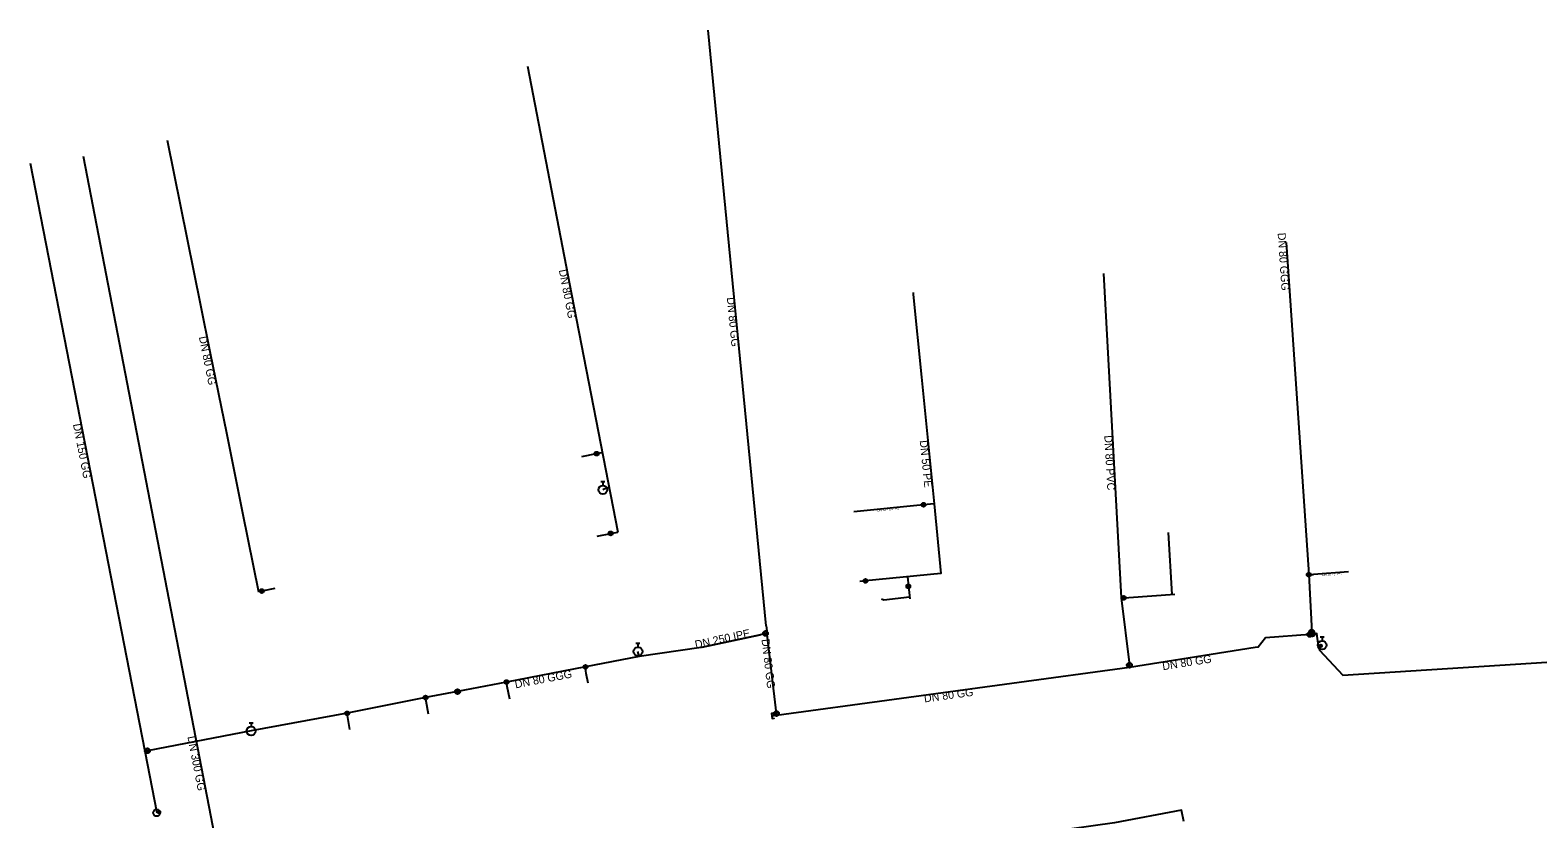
# Model space of a CAD drawing. Extents: x -452548 to -451108, y -1100145 to -1099658.
# Drawn here: x -452039.2 to -451735.5, y -1099878.8 to -1099719.9 of the extents above; entities that cross this region are included whole.
import ezdxf

# ---------------------------------------------------------------- set-up
doc = ezdxf.new("R2010")
doc.units = 0
for name, color, linetype in [('_hydrantova_odbocka_', 7, 'Continuous'), ('_pripojka_prevzato_z_dokumentace_', 7, 'Continuous'), ('_pripojka_priblizne_', 7, 'Continuous'), ('_voda_smvak_prevzato_z_dokumentace_', 7, 'Continuous'), ('_vodovodni_chranicka_', 7, 'Continuous'), ('Default', 7, 'Continuous'), ('MoLevel 27', 7, 'Continuous'), ('MoLevel 28', 7, 'Continuous'), ('MoLevel 30', 7, 'Continuous'), ('MoLevel 42', 7, 'Continuous'), ('MoLevel 43', 7, 'Continuous'), ('MoLevel 46', 7, 'Continuous'), ('MoLevel 53', 7, 'Continuous'), ('MoLevel 55', 7, 'Continuous'), ('MoLevel 60', 7, 'Continuous')]:
    doc.layers.add(name, color=color, linetype=linetype)

# ---------------------------------------------------------------- blocks, each defined once
blk = doc.blocks.new('_uzaver_')
at = {"layer": 'Default'}
for p, q in [((-0.000035, -0.000035), (0.000035, 0.000035)), ((0.000035, -0.000035), (-0.000035, 0.000035))]:
    blk.add_line(p, q, dxfattribs=at)
for radius in [0.00005, 0.0000025]:
    blk.add_circle((0, 0), radius, dxfattribs=at)
blk = doc.blocks.new('_uzaver_pripojka_')
at = {"layer": 'Default'}
for p, q in [((-0.000035, -0.000035), (0.000035, 0.000035)), ((0.000035, -0.000035), (-0.000035, 0.000035))]:
    blk.add_line(p, q, dxfattribs=at)
for radius in [0.00005, 0.0000025]:
    blk.add_circle((0, 0), radius, dxfattribs=at)
blk = doc.blocks.new('_hydrant_voda_')
at = {"layer": 'Default'}
for p, q in [((-0.000023, 0.000095), (0.000023, 0.000095)), ((0, 0.000095), (0, 0.00005))]:
    blk.add_line(p, q, dxfattribs=at)
blk.add_circle((0, 0), 0.00005, dxfattribs=at)
blk = doc.blocks.new('_zaslepeni_')
at = {"layer": 'Default'}
blk.add_lwpolyline([(-0.00004, -0.00005), (0, -0.00005), (0, 0.00005), (-0.00004, 0.00005), (-0.00004, 0.00005)], dxfattribs=at)
blk = doc.blocks.new('_sachta_voda_')
at = {"layer": 'Default'}
blk.add_circle((0, 0), 0.000035, dxfattribs=at)
blk = doc.blocks.new('_poklop_voda_')
at = {"layer": 'Default'}
blk.add_lwpolyline([(-0.00002, 0.00002), (0.00002, 0.00002), (0.00002, -0.00002), (-0.00002, -0.00002), (-0.00002, 0.00002)], dxfattribs=at)

msp = doc.modelspace()

# ---------------------------------------------------------------- linework, layer by layer
at = {"layer": '_hydrantova_odbocka_'}
for points in [[(-451922.54, -1099812.09), (-451923.04, -1099812.19), (-451923.79, -1099812.49)], [(-451779.62, -1099844.01), (-451779.19, -1099843.92), (-451778.92, -1099843.79)], [(-451916.47, -1099846.08), (-451916.6, -1099845.56), (-451916.73, -1099845.07)]]:
    msp.add_lwpolyline(points, dxfattribs=at)
at = {"layer": '_pripojka_prevzato_z_dokumentace_'}
for p, q in [((-451781.6, -1099829.59), (-451780.63, -1099829.54)), ((-451773.61, -1099829.04), (-451780.63, -1099829.54)), ((-451872.01, -1099830.93), (-451870.9, -1099830.84)), ((-451926.72, -1099851.48), (-451927.13, -1099849.51)), ((-451942.51, -1099854.65), (-451943.07, -1099852.15)), ((-451958.9, -1099857.7), (-451959.36, -1099855.05)), ((-451974.79, -1099860.76), (-451975.14, -1099858.33))]:
    msp.add_line(p, q, dxfattribs=at)
for points in [[(-451928.03, -1099805.8), (-451925.05, -1099805.22), (-451923.92, -1099805)], [(-451857.09, -1099815.31), (-451859.19, -1099815.52), (-451873.23, -1099816.92)], [(-451924.94, -1099821.82), (-451922.21, -1099821.28), (-451920.81, -1099821.02)], [(-451989.9, -1099832.39), (-451992.5, -1099832.89), (-451993.15, -1099833.02)], [(-451862.45, -1099830), (-451862.26, -1099831.94), (-451861.98, -1099834.43)], [(-451819.38, -1099834.29), (-451818.87, -1099834.26), (-451817.85, -1099834.18), (-451808.61, -1099833.55)], [(-451927.13, -1099849.51), (-451927.19, -1099848.95), (-451927.28, -1099848.16)], [(-451943.07, -1099852.15), (-451943.13, -1099851.65), (-451943.19, -1099851.22)], [(-451959.36, -1099855.05), (-451959.42, -1099854.76), (-451959.49, -1099854.35)], [(-451975.14, -1099858.33), (-451975.22, -1099857.94), (-451975.3, -1099857.52)]]:
    msp.add_lwpolyline(points, dxfattribs=at)
at = {"layer": '_pripojka_priblizne_'}
msp.add_line((-451809.14, -1099833.58), (-451809.83, -1099821.13), dxfattribs=at)
msp.add_lwpolyline([(-451862.01, -1099834.12), (-451867.18, -1099834.74), (-451867.66, -1099834.53)], dxfattribs=at)
at = {"layer": '_voda_smvak_prevzato_z_dokumentace_'}
for p, q in [((-451890.88, -1099839.87), (-451902.55, -1099719.92)), ((-452039.15, -1099746.71), (-452016.08, -1099865.12)), ((-452003.12, -1099876.35), (-452028.42, -1099745.38)), ((-451890.72, -1099841.41), (-451891.03, -1099841.43)), ((-451888.83, -1099857.57), (-451890.71, -1099841.66)), ((-451780.99, -1099841.55), (-451781.4, -1099841.63)), ((-451781.01, -1099841.17), (-451780.99, -1099841.55)), ((-451780.87, -1099841.53), (-451780.99, -1099841.55)), ((-451792.38, -1099844.27), (-451817.68, -1099848.29)), ((-451817.72, -1099847.83), (-451817.68, -1099848.29)), ((-451817.68, -1099848.29), (-451888.79, -1099857.95)), ((-451888.79, -1099857.95), (-451889.77, -1099858.06)), ((-451888.79, -1099857.95), (-451888.83, -1099857.57)), ((-451994.65, -1099861.08), (-452015.54, -1099865.07)), ((-452015.53, -1099865.07), (-452016.08, -1099865.12)), ((-452016.08, -1099865.12), (-452013.65, -1099877.56))]:
    msp.add_line(p, q, dxfattribs=at)
for points in [[(-451939, -1099727.2), (-451930.1, -1099773.11), (-451920.81, -1099821.02)], [(-452011.58, -1099742.08), (-452004.84, -1099775.33), (-452002.89, -1099784.98), (-451999.63, -1099801.02), (-451996.36, -1099817.17), (-451993.15, -1099833.02)], [(-451786.13, -1099762.72), (-451785.48, -1099772.43), (-451781.6, -1099829.59), (-451781.01, -1099841.17)], [(-451822.98, -1099768.93), (-451819.38, -1099834.29), (-451817.72, -1099847.83)], [(-451861.32, -1099772.73), (-451861.28, -1099773.14), (-451859.62, -1099789.82), (-451857.09, -1099815.31), (-451855.7, -1099829.33), (-451870.9, -1099830.84)], [(-451891.03, -1099841.43), (-451892.01, -1099841.7), (-451903.97, -1099844.26), (-451916.47, -1099846.08), (-451927.28, -1099848.16), (-451943.19, -1099851.22), (-451953.07, -1099853.15)], [(-451890.88, -1099839.87), (-451890.72, -1099841.41), (-451890.71, -1099841.66)], [(-451781.4, -1099841.63), (-451790.31, -1099842.31), (-451791.77, -1099844.2), (-451792.38, -1099844.27)], [(-451779.64, -1099843.93), (-451779.98, -1099841.43), (-451780.87, -1099841.53), (-451780.87, -1099841.53)], [(-451779.64, -1099843.93), (-451779.43, -1099844.82), (-451774.74, -1099849.86), (-451705.18, -1099845.41), (-451704.49, -1099845.24)], [(-451953.07, -1099853.15), (-451959.49, -1099854.35), (-451975.3, -1099857.52), (-451994.65, -1099861.08)], [(-451978.75, -1099992.6), (-451982.47, -1099975.18), (-451984.85, -1099964.79), (-451987.8, -1099951.84), (-451992.55, -1099931.06), (-452003.12, -1099876.35)], [(-451806.74, -1099879.29), (-451807.26, -1099877.03), (-451820.76, -1099879.61), (-451834.59, -1099881.54), (-451839.74, -1099882.46), (-451857.41, -1099885.86), (-451884.96, -1099892.07), (-451884.96, -1099892.47)]]:
    msp.add_lwpolyline(points, dxfattribs=at)
at = {"layer": '_vodovodni_chranicka_'}
msp.add_line((-451903.78, -1099844.21), (-451892.1, -1099841.68), dxfattribs=at)

# ---------------------------------------------------------------- block references
at = {"layer": 'MoLevel 27'}
for p, xscale, yscale, rotation in [((-451891.03, -1099841.43), 10000.000000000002, 10000, 7.800187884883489), ((-451781.4, -1099841.63), 10000, 10000.000000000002, 7.23692202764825), ((-451781.01, -1099841.17), 10000.000000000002, 9999.999999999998, 92.8395243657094), ((-451780.87, -1099841.53), 10000, 10000, 4.590543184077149), ((-451817.72, -1099847.83), 10000.000000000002, 10000, 97.0037214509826), ((-451953.07, -1099853.15), 10000, 10000.000000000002, 9.278058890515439), ((-451888.83, -1099857.57), 10000, 9999.999999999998, 7.445354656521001), ((-452015.53, -1099865.07), 10000, 9999.999999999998, 8.790277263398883)]:
    msp.add_blockref('_uzaver_', p, dxfattribs=dict(at, xscale=xscale, yscale=yscale, rotation=rotation))
at = {"layer": 'MoLevel 27', "xscale": 5000, "yscale": 5000}
msp.add_blockref('_uzaver_', (-451779.19, -1099843.92), dxfattribs=at)
at = {"layer": 'MoLevel 28', "xscale": 17636.68430335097, "yscale": 17636.68430335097}
for p in [(-451923.79, -1099812.49), (-451916.72, -1099845.07), (-451778.92, -1099843.79), (-451994.66, -1099861.08)]:
    msp.add_blockref('_hydrant_voda_', p, dxfattribs=at)
at = {"layer": 'MoLevel 30', "xscale": 20000, "yscale": 20000}
msp.add_blockref('_sachta_voda_', (-452013.65, -1099877.56), dxfattribs=at)
at = {"layer": 'MoLevel 42', "xscale": 10000, "yscale": 10000}
msp.add_blockref('_poklop_voda_', (-452013.17, -1099877.4), dxfattribs=at)
at = {"layer": 'MoLevel 43', "xscale": 9999.999999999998, "yscale": 9999.999999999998, "rotation": -173.66622991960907}
msp.add_blockref('_zaslepeni_', (-451889.77, -1099858.06), dxfattribs=at)
at = {"layer": 'MoLevel 53', "xscale": 7999.999999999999, "yscale": 7999.999999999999}
for p in [(-451925.05, -1099805.22), (-451859.19, -1099815.52), (-451922.21, -1099821.28), (-451781.6, -1099829.59), (-451992.5, -1099832.89), (-451870.9, -1099830.84), (-451862.26, -1099831.94), (-451818.87, -1099834.26), (-451927.28, -1099848.16), (-451943.19, -1099851.22), (-451959.49, -1099854.35), (-451975.3, -1099857.52)]:
    msp.add_blockref('_uzaver_pripojka_', p, dxfattribs=at)

# ---------------------------------------------------------------- texts
at = {"layer": 'MoLevel 46'}
for s, rotation, p in [('DN 80 GGG', 273.8654, (-451787.87, -1099760.78)), ('DN 80 GG', 280.9726, (-451932.67, -1099768.26)), ('DN 80 GG', 275.555, (-451898.83, -1099773.79)), ('DN 80 GG', 281.4609, (-452005.18, -1099781.73)), ('DN 150 GG', 281.0276, (-452030.54, -1099799.32)), ('DN 80 PVC', 273.1493, (-451822.79, -1099801.56)), ('DN 50 PE', 275.6757, (-451859.97, -1099802.59)), ('DN 80 GG', 276.7516, (-451891.84, -1099842.64)), ('DN 80 GG', 9.0109, (-451810.97, -1099848.85)), ('DN 80 GGG', 10.8966, (-451941.37, -1099852.5)), ('DN 80 GG', 7.7419, (-451859, -1099855.33)), ('DN 300 GG', 280.9314, (-452007.48, -1099862.24))]:
    msp.add_text(s, height=1.605, rotation=rotation, dxfattribs=at).set_placement(p)
at = {"layer": 'MoLevel 55'}
for s, rotation, p in [("DN 32 - 5/4'' PE", 5.6754, (-451868.49, -1099816.9)), ("DN 25 - 1'' PE", 4.0943, (-451778.9, -1099829.88))]:
    msp.add_text(s, height=0.455, rotation=rotation, dxfattribs=at).set_placement(p)
at = {"layer": 'MoLevel 60'}
msp.add_text('DN 250 IPE', height=1.605, rotation=12.222, dxfattribs=at).set_placement((-451905.07, -1099844.49))

doc.saveas('drawing.dxf')
